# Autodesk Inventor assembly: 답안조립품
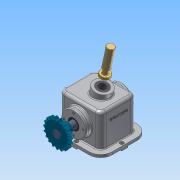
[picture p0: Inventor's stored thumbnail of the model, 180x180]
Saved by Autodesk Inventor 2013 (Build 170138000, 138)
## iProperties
Created: 2014-11
Part Number: 답안조립품
Document SubType Name: Assembly
Designer: Administrator
Author: Administrator
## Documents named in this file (13)
- C:\Users\Administrator\Desktop\441123V1007\답안조립품.iam
- C:\Users\Administrator\Desktop\441123V1007\본체.ipt
- C:\Users\Administrator\Desktop\441123V1007\5-체인 스프로킷.ipt
- C:\Users\Administrator\Desktop\441123V1007\M4x0.5.ipt
- C:\Users\Administrator\Desktop\441123V1007\뒤커버.ipt
- C:\Users\Administrator\Desktop\441123V1007\멈춤나사 M5x0.5.ipt
- C:\Users\Administrator\Desktop\441123V1007\베어링 6205.ipt
- C:\Users\Administrator\Desktop\441123V1007\부시.ipt
- C:\Users\Administrator\Desktop\441123V1007\슬라이드.ipt
- C:\Users\Administrator\Desktop\441123V1007\앞커버.ipt
- C:\Users\Administrator\Desktop\441123V1007\오일실.ipt
- C:\Users\Administrator\Desktop\441123V1007\키 8x8.ipt
- C:\Users\Administrator\Desktop\441123V1007\편심축.ipt
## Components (9 placed, 2 different names)
1. 5-체인 스프로킷:1 — 플러쉬:1
2. M4x0.5:2
3. M4x0.5:3
4. M4x0.5:4
5. M4x0.5:5
6. M4x0.5:1
7. M4x0.5:6
8. M4x0.5:7
9. M4x0.5:8
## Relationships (1: Flush 1)
- 플러쉬:1 [Flush]: 5-체인 스프로킷:1
